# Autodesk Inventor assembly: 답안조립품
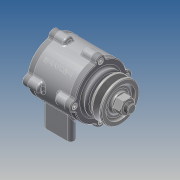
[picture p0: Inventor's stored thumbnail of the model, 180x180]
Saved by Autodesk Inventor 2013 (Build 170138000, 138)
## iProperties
Created: 2015-03
Part Number: 답안조립품
Document SubType Name: Assembly
Designer: kb
Author: kb
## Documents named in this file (11)
- C:\Users\kb\Desktop\450305V1041\답안조립품.iam
- C:\Users\kb\Desktop\450305V1041\1-본체.ipt
- C:\Users\kb\Desktop\450305V1041\M 4 x 12.ipt
- C:\Users\kb\Desktop\450305V1041\V벨트풀리.ipt
- C:\Users\kb\Desktop\450305V1041\너트 M12x1.25.ipt
- C:\Users\kb\Desktop\450305V1041\베어링 6204.ipt
- C:\Users\kb\Desktop\450305V1041\오일실.ipt
- C:\Users\kb\Desktop\450305V1041\축.ipt
- C:\Users\kb\Desktop\450305V1041\커버.ipt
- C:\Users\kb\Desktop\450305V1041\커버2.ipt
- C:\Users\kb\Desktop\450305V1041\키(4 x 4 x 12).ipt
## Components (15 placed, 7 different names)
1. 1-본체:1
2. 그루브 풀리1:1
3. KS B 1012 클래스 1 일반 - 미터 M12x1.25:1
4. KS B 2023 6204 - 20 x 47 x 14:1
5. KS B 2804 D D - 20 32 8:1
6. KS B 1311 (I) 4 x 4 x 12:1
7. KS B 2023 6204 - 20 x 47 x 14:2
8. KS B 1003 - 미터 M 4 x 12:1
9. KS B 1003 - 미터 M 4 x 12:3
10. KS B 1003 - 미터 M 4 x 12:4
11. KS B 1003 - 미터 M 4 x 12:5
12. KS B 1003 - 미터 M 4 x 12:2
13. KS B 1003 - 미터 M 4 x 12:6
14. KS B 1003 - 미터 M 4 x 12:7
15. KS B 1003 - 미터 M 4 x 12:8
